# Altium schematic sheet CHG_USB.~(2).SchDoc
size A; SheetNumber: 1; SheetTotal: 1
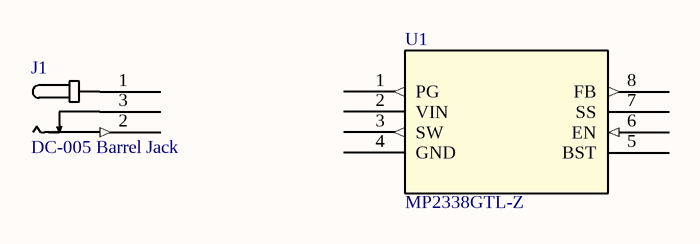
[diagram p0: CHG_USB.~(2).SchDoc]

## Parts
J1  DC-005 Barrel Jack
U1  MP2338GTL-Z

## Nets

Not connected (* = marked no-connect by the designer): J1 1(VIN) 2(SW) 3(GND); U1 1(PG) 2(VIN) 3(SW) 4(GND) 5(BST) 6(EN) 7(SS) 8(FB)

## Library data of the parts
J1 = DC-005 Barrel Jack: Barrel Jack to simplify PCB complexity
U1 = MP2338GTL-Z: MP2338 IC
